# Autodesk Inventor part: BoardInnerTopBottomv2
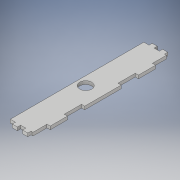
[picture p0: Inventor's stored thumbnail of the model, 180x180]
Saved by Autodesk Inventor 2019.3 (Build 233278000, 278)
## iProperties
Created: 2020-03
Part Number: BoardInnerTopBottomv2
Material: Generic
Document SubType Name: Modeling
Designer: KrystynWikoff
Density: 1 g/cm^3
Appearance: Default
Author: KrystynWikoff
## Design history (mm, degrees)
sketch "Sketch1"
  geometry: L1 (0, 0)-(19.05, 0); L2 (19.05, 0)-(19.05, -103.1); L3 (19.05, -103.1)-(0, -103.1); L4 (0, -103.1)-(0, 0)
  constraints: 8 end point, 2 parallel, 1 horizontal, 1 perpendicular
  dimensions: "d0" = 19.05 distance of L1.start L1.end; "d1" = 103.1 distance of L3.end L1.start
extrude "Extrusion1" new body sketch "Sketch1" distance "d2" = 2.3622; taper "d3" = 0 deg
sketch "Sketch2" dims "d11" = 25.4, "d20" = 25.4
  geometry: L1 (-19.05, 0)-(0, 0) reference; L2 (0, 0)-(-3.81, 0); L3 (-3.81, 0)-(-3.81, 2.362); L4 (-3.81, 2.362)-(0, 2.362); L5 (0, 2.362)-(0, 0); L6 (-7.62, 0)-(-11.43, 0); L7 (-11.43, 0)-(-11.43, 2.362); L8 (-11.43, 2.362)-(-7.62, 2.362); L9 (-7.62, 2.362)-(-7.62, 0); L10 (-15.24, 0)-(-19.05, 0); L11 (-19.05, 0)-(-19.05, 2.362); L12 (-19.05, 2.362)-(-15.24, 2.362); L13 (-15.24, 2.362)-(-15.24, 0); L14 (0, 103.1)-(-19.05, 103.1) reference; L15 (0, 103.1)-(-3.81, 103.1); L16 (-3.81, 103.1)-(-3.81, 100.738); L17 (-3.81, 100.738)-(0, 100.738); L18 (0, 100.738)-(0, 103.1); L19 (-11.43, 100.738)-(-7.62, 100.738); L20 (-11.43, 103.1)-(-11.43, 100.738); L21 (-7.62, 103.1)-(-11.43, 103.1); L22 (-7.62, 100.738)-(-7.62, 103.1); L23 (-19.05, 100.738)-(-15.24, 100.738); L24 (-19.05, 103.1)-(-19.05, 100.738); L25 (-15.24, 103.1)-(-19.05, 103.1); L26 (-15.24, 100.738)-(-15.24, 103.1)
  constraints: 48 end point, 4 horizontal, 4 parallel, 2 perpendicular, 32 other
  dimensions: "d4" = 3.81 distance of L3.end L4.end; "d5" = 2.3622 distance of L2.end L3.end; "d8" = 7.62 distance of L3.end L7.end; "d13" = 3.81 distance of L16.end L17.end; "d14" = 2.3622 distance of L15.end L16.end; "d17" = 7.62 distance of L16.end L19.start
extrude "Extrusion2" cut sketch "Sketch2" distance "d22" = 2.3622; taper "d23" = 0 deg
sketch "Sketch3" dims "d32" = 25.4, "d43" = 25.4
  geometry: L1 (0, 100.738)-(0, 2.362) reference; L2 (0, 0)-(-2.362, 0); L3 (-2.362, 0)-(-2.362, 12.7); L4 (-2.362, 12.7)-(0, 12.7); L5 (0, 12.7)-(0, 0); L6 (-7.62, 0)-(-3.81, 0) reference; L7 (0, 25.4)-(-2.362, 25.4); L8 (-2.362, 25.4)-(-2.362, 38.1); L9 (-2.362, 38.1)-(0, 38.1); L10 (0, 38.1)-(0, 25.4); L11 (0, 103.1)-(-2.362, 103.1); L12 (-2.362, 103.1)-(-2.362, 90.4); L13 (-2.362, 90.4)-(0, 90.4); L14 (0, 90.4)-(0, 103.1); L15 (-3.81, 103.1)-(-7.62, 103.1) reference; L16 (-2.362, 65)-(0, 65); L17 (0, 65)-(0, 77.7); L18 (-2.362, 77.7)-(-2.362, 65); L19 (0, 77.7)-(-2.362, 77.7); 1 further point
  constraints: 32 end point, 4 parallel, 2 horizontal, 2 perpendicular, 2 vertical, 1 point on line, 16 other
  dimensions: "d24" = 0 distance between parallel lines of L6 L2; "d25" = 12.7 distance of L2.end L3.end; "d26" = 2.3622 distance of L2.start L2.end; "d29" = 25.4 distance of L2.start L7.start; "d34" = 2.3622 distance of L12.end L13.end; "d35" = 12.7 distance of L11.end L12.end; "d36" = 0 distance between parallel lines of L15 L11; "d37" = 2.3622 distance between parallel lines of L1 L12; "d40" = 25.4 distance of L13.end L16.end
extrude "Extrusion3" cut sketch "Sketch3" distance "d45" = 2.3622; taper "d46" = 0 deg
sketch "Sketch4"
  geometry: L1 (0, 38.1)-(0, 65) reference; L2 (-11.43, 103.1)-(-15.24, 103.1) reference; C1 r 4.445 at (-12.7, 51.538); 1 further point
  constraints: 1 centre point
  dimensions: "d47" = 8.89 diameter of C1; "d48" = 12.7 distance from line of L1 C1.centre; "d49" = 51.562 distance from line of L2 C1.centre
extrude "Extrusion4" cut sketch "Sketch4" distance "d50" = 25.4; taper "d51" = 0 deg
body "Solid1"
